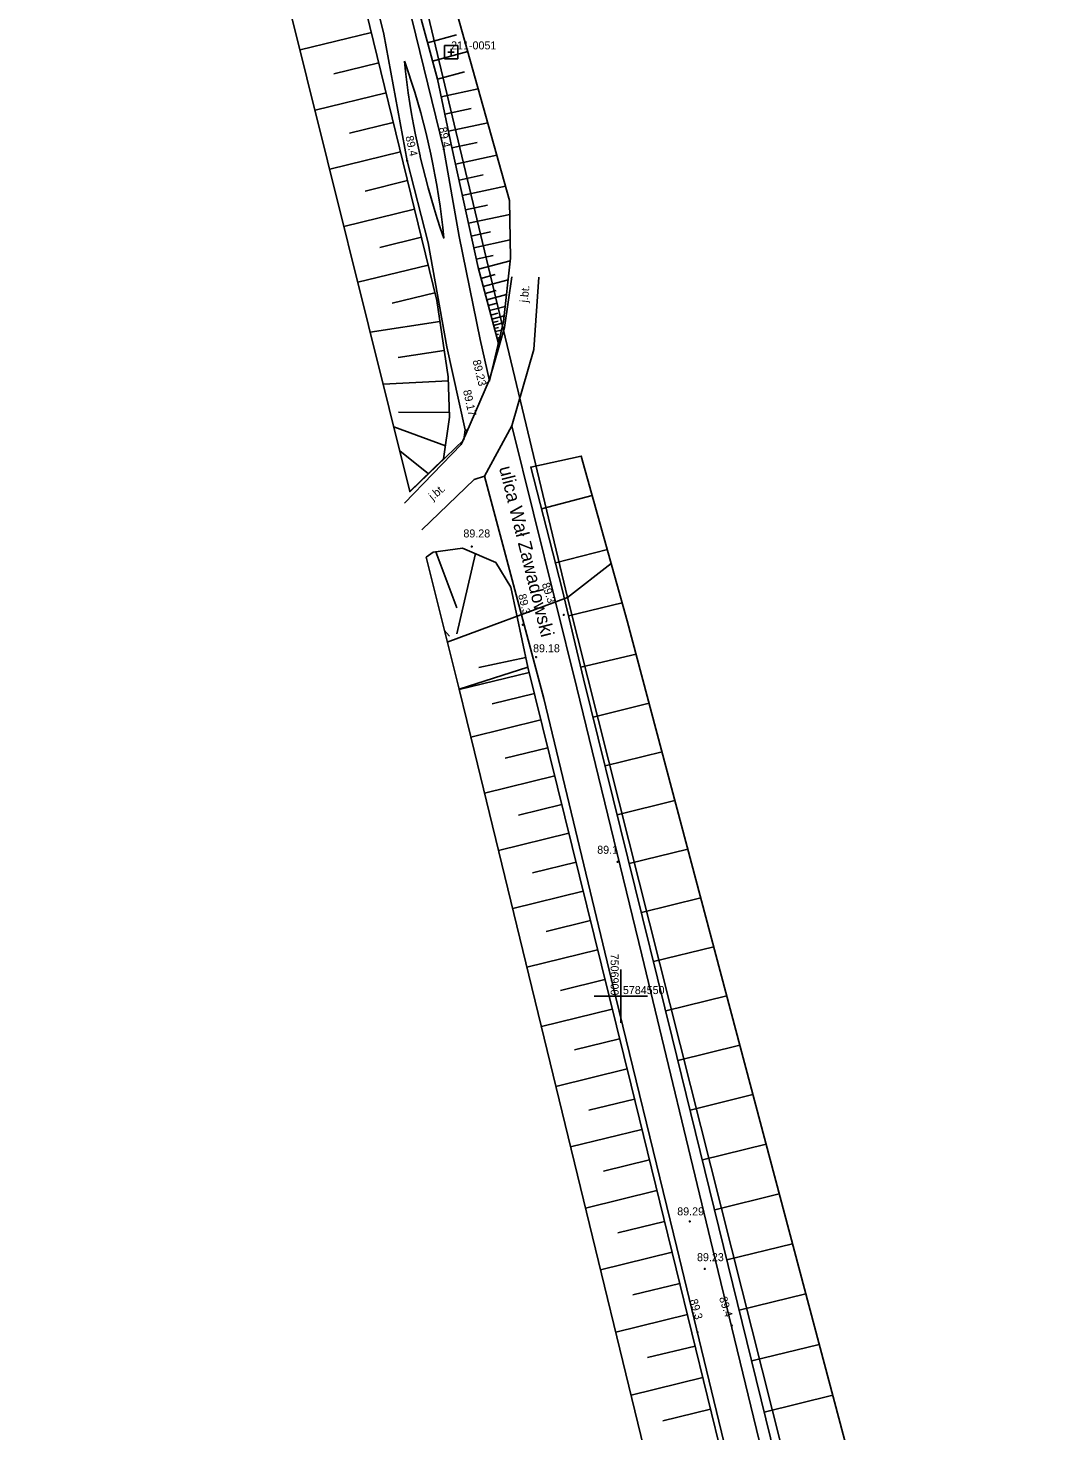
# Model space of a CAD drawing. Extents: x 7506075 to 7506993, y 5784375 to 5786367.
# Drawn here: x 7506844.5 to 7506940.4, y 5784509.3 to 5784640.7 of the extents above; entities that cross this region are included whole.
import ezdxf

# ---------------------------------------------------------------- set-up
doc = ezdxf.new("R2010")
doc.units = 0
for name, color, linetype in [('000 Inne (niezydentyfikowane)', 7, 'Continuous'), ('203-punkt graniczny', 7, 'Continuous'), ('216-obręb ewidencyjny', 7, 'Continuous'), ('218-kontur użytku gruntowego', 7, 'Continuous'), ('219-działka ewidencyjna', 7, 'Continuous'), ('994-Nazwa ulicy', 7, 'Continuous'), ('jezdnia', 7, 'Continuous'), ('jezdnia-Atr17', 7, 'Continuous'), ('pikieta naturalna', 7, 'Continuous'), ('pikieta naturalna-Atr2', 7, 'Continuous'), ('pikieta sztuczna', 7, 'Continuous'), ('pikieta sztuczna-Atr2', 7, 'Continuous'), ('skarpa nieumocniona', 7, 'Continuous'), ('skarpa umocniona', 7, 'Continuous'), ('Szczegółowa osnowa geodezyjna pozioma', 7, 'Continuous'), ('Szczegółowa osnowa geodezyjna pozioma-Atr103', 7, 'Continuous'), ('Wstawianie ramki sekcyjnej z opisem', 7, 'Continuous')]:
    doc.layers.add(name, color=color, linetype=linetype)

# ---------------------------------------------------------------- blocks, each defined once
blk = doc.blocks.new('PW01')
blk.add_circle((0, 0), 0.045)
blk = doc.blocks.new('203')
blk.add_circle((0, 0), 0.045)
blk = doc.blocks.new('OSSP')
for p, q in [((-0.626, 0.625), (-0.626, -0.625)), ((-0.626, 0.625), (-0.626, -0.625)), ((0.624, 0.625), (-0.626, 0.625)), ((0.624, 0.625), (-0.626, 0.625)), ((0.3, 0), (-0.3, 0)), ((0.3, 0), (-0.3, 0)), ((0, -0.3), (0, 0.3)), ((0, -0.3), (0, 0.3)), ((0.624, -0.625), (0.624, 0.625)), ((0.624, -0.625), (0.624, 0.625)), ((-0.626, -0.625), (0.624, -0.625)), ((-0.626, -0.625), (0.624, -0.625))]:
    blk.add_line(p, q)

msp = doc.modelspace()

# ---------------------------------------------------------------- linework, layer by layer
at = {"layer": '000 Inne (niezydentyfikowane)'}
for p, q in [((7506876.63, 5784640.32), (7506869.943, 5784638.687)), ((7506881.89, 5784639.36), (7506884.6, 5784640.09)), ((7506882.36, 5784637.63), (7506885.659, 5784638.524)), ((7506877.32, 5784637.47), (7506873.12, 5784636.44)), ((7506882.81, 5784635.95), (7506885.35, 5784636.64)), ((7506878.01, 5784634.65), (7506871.349, 5784633.029)), ((7506883.17, 5784634.29), (7506886.641, 5784635.023)), ((7506883.51, 5784632.66), (7506885.97, 5784633.18)), ((7506878.68, 5784631.87), (7506874.59, 5784630.88)), ((7506883.85, 5784631.06), (7506887.533, 5784631.839)), ((7506879.35, 5784629.13), (7506872.72, 5784627.514)), ((7506884.18, 5784629.5), (7506886.54, 5784630.01)), ((7506884.51, 5784627.97), (7506888.383, 5784628.807)), ((7506880.01, 5784626.43), (7506876.03, 5784625.46)), ((7506884.84, 5784626.48), (7506887.1, 5784626.97)), ((7506885.15, 5784625.04), (7506889.192, 5784625.922)), ((7506880.66, 5784623.76), (7506874.053, 5784622.148)), ((7506885.45, 5784623.69), (7506887.51, 5784624.14)), ((7506885.72, 5784622.43), (7506889.59, 5784623.27)), ((7506881.31, 5784621.12), (7506877.42, 5784620.18)), ((7506885.98, 5784621.24), (7506887.8, 5784621.64)), ((7506886.22, 5784620.13), (7506889.64, 5784620.87)), ((7506881.94, 5784618.52), (7506875.354, 5784616.914)), ((7506886.45, 5784619.08), (7506888.05, 5784619.43)), ((7506886.67, 5784618.12), (7506889.64, 5784618.91)), ((7506886.9, 5784617.27), (7506888.22, 5784617.62)), ((7506887.1, 5784616.51), (7506889.45, 5784617.14)), ((7506882.58, 5784615.91), (7506878.57, 5784614.94)), ((7506887.28, 5784615.84), (7506888.32, 5784616.12)), ((7506887.44, 5784615.25), (7506889.29, 5784615.75)), ((7506887.58, 5784614.72), (7506888.4, 5784614.94)), ((7506887.71, 5784614.25), (7506889.17, 5784614.64)), ((7506883.05, 5784613.23), (7506876.516, 5784612.237)), ((7506887.82, 5784613.83), (7506888.47, 5784614.01)), ((7506887.92, 5784613.46), (7506889.07, 5784613.77)), ((7506888.01, 5784613.14), (7506888.52, 5784613.27)), ((7506888.08, 5784612.85), (7506888.98, 5784613.09)), ((7506888.15, 5784612.58), (7506888.53, 5784612.68)), ((7506888.24, 5784612.28), (7506888.82, 5784612.43)), ((7506888.32, 5784611.97), (7506888.53, 5784612.03)), ((7506888.4, 5784611.66), (7506888.66, 5784611.73)), ((7506883.46, 5784610.51), (7506879.15, 5784609.86)), ((7506883.84, 5784607.67), (7506877.727, 5784607.366)), ((7506883.95, 5784604.69), (7506879.16, 5784604.74)), ((7506883.58, 5784601.58), (7506878.723, 5784603.358)), ((7506881.98, 5784598.97), (7506879.285, 5784601.096)), ((7506892.57, 5784595.69), (7506897.321, 5784596.922)), ((7506882.67, 5784591.64), (7506884.64, 5784586.41)), ((7506886.37, 5784591.49), (7506884.65, 5784583.95)), ((7506893.88, 5784590.6), (7506898.741, 5784591.856)), ((7506895.11, 5784585.65), (7506900.144, 5784586.852)), ((7506883.458, 5784584.305), (7506883.94, 5784583.73)), ((7506891.11, 5784581.73), (7506886.7, 5784580.8)), ((7506896.26, 5784580.83), (7506901.439, 5784582.064)), ((7506891.42, 5784580.35), (7506884.844, 5784578.73)), ((7506891.91, 5784578.38), (7506887.94, 5784577.4)), ((7506897.41, 5784576.15), (7506902.663, 5784577.45)), ((7506892.52, 5784575.9), (7506885.949, 5784574.284)), ((7506893.16, 5784573.29), (7506889.16, 5784572.3)), ((7506898.54, 5784571.58), (7506903.87, 5784572.898)), ((7506893.82, 5784570.64), (7506887.238, 5784569.015)), ((7506899.67, 5784567.01), (7506905.076, 5784568.354)), ((7506894.48, 5784567.96), (7506890.43, 5784566.96)), ((7506895.14, 5784565.27), (7506888.546, 5784563.642)), ((7506900.8, 5784562.43), (7506906.287, 5784563.79)), ((7506895.81, 5784562.56), (7506891.72, 5784561.55)), ((7506896.48, 5784559.83), (7506889.869, 5784558.207)), ((7506901.94, 5784557.84), (7506907.5, 5784559.214)), ((7506897.16, 5784557.1), (7506893.02, 5784556.08)), ((7506897.83, 5784554.35), (7506891.208, 5784552.708)), ((7506903.07, 5784553.24), (7506908.715, 5784554.634)), ((7506898.52, 5784551.58), (7506894.34, 5784550.55)), ((7506904.22, 5784548.62), (7506909.936, 5784550.032)), ((7506899.2, 5784548.8), (7506892.559, 5784547.156)), ((7506899.89, 5784546), (7506895.67, 5784544.96)), ((7506905.36, 5784543.98), (7506911.163, 5784545.405)), ((7506900.59, 5784543.19), (7506893.925, 5784541.543)), ((7506906.5, 5784539.33), (7506912.391, 5784540.775)), ((7506901.28, 5784540.36), (7506897.01, 5784539.31)), ((7506901.98, 5784537.52), (7506895.304, 5784535.88)), ((7506907.65, 5784534.67), (7506913.622, 5784536.135)), ((7506902.68, 5784534.66), (7506898.37, 5784533.6)), ((7506903.39, 5784531.79), (7506896.699, 5784530.148)), ((7506908.8, 5784529.98), (7506914.858, 5784531.475)), ((7506904.1, 5784528.9), (7506899.74, 5784527.83)), ((7506909.95, 5784525.28), (7506916.1, 5784526.791)), ((7506904.81, 5784526), (7506898.109, 5784524.355)), ((7506905.52, 5784523.09), (7506901.12, 5784522.01)), ((7506911.11, 5784520.57), (7506917.345, 5784522.098)), ((7506906.24, 5784520.16), (7506899.53, 5784518.52)), ((7506906.96, 5784517.22), (7506902.52, 5784516.13)), ((7506912.27, 5784515.82), (7506918.599, 5784517.373)), ((7506907.68, 5784514.26), (7506900.965, 5784512.625)), ((7506913.45, 5784511.03), (7506919.863, 5784512.608)), ((7506908.41, 5784511.3), (7506903.93, 5784510.2))]:
    msp.add_line(p, q, dxfattribs=at)
at = {"layer": '216-obręb ewidencyjny'}
for points in [[(7506895.02, 5784587.37), (7506880.51, 5784647.95)], [(7506895.02, 5784587.37), (7506883.74, 5784583.171)], [(7506940.165, 5784408.278), (7506895.02, 5784587.37)]]:
    msp.add_lwpolyline(points, dxfattribs=at)
at = {"layer": '218-kontur użytku gruntowego'}
for points in [[(7506895.02, 5784587.37), (7506880.51, 5784647.95)], [(7506883.74, 5784583.171), (7506895.02, 5784587.37)], [(7506895.02, 5784587.37), (7506940.165, 5784408.278)]]:
    msp.add_lwpolyline(points, dxfattribs=at)
at = {"layer": '219-działka ewidencyjna'}
for points in [[(7506895.02, 5784587.37), (7506880.51, 5784647.95)], [(7506895.02, 5784587.37), (7506880.51, 5784647.95)], [(7506895.02, 5784587.37), (7506899.111, 5784590.537)], [(7506895.02, 5784587.37), (7506883.74, 5784583.171)], [(7506883.74, 5784583.171), (7506895.02, 5784587.37)], [(7506940.165, 5784408.278), (7506895.02, 5784587.37)], [(7506940.165, 5784408.278), (7506895.02, 5784587.37)]]:
    msp.add_lwpolyline(points, dxfattribs=at)
at = {"layer": 'jezdnia'}
for p, q in [((7506889.792, 5784617.412), (7506889.089, 5784612.675)), ((7506891.84, 5784610.615), (7506892.321, 5784617.389)), ((7506889.089, 5784612.675), (7506887.706, 5784607.784)), ((7506889.796, 5784603.456), (7506891.84, 5784610.615)), ((7506885.48, 5784602.658), (7506887.706, 5784607.784)), ((7506885.056, 5784601.715), (7506885.48, 5784602.658)), ((7506887.218, 5784598.723), (7506889.796, 5784603.456)), ((7506895.88, 5784578.885), (7506889.796, 5784603.456)), ((7506879.716, 5784596.202), (7506885.056, 5784601.715)), ((7506886.258, 5784598.437), (7506887.218, 5784598.723)), ((7506887.218, 5784598.723), (7506892.804, 5784577.898)), ((7506886.258, 5784598.437), (7506881.347, 5784593.717)), ((7506901.982, 5784553.885), (7506895.88, 5784578.885)), ((7506892.804, 5784577.898), (7506898.907, 5784552.427)), ((7506908.634, 5784526.274), (7506901.982, 5784553.885)), ((7506898.907, 5784552.427), (7506905.24, 5784526.442)), ((7506905.24, 5784526.442), (7506912.45, 5784496.722)), ((7506915.601, 5784497.452), (7506908.634, 5784526.274))]:
    msp.add_line(p, q, dxfattribs=at)
for points in [[(7506873.05, 5784671.33), (7506880.78, 5784640.05), (7506883.42, 5784629.35), (7506884.86, 5784621.19), (7506886.83, 5784611.55)], [(7506883.71, 5784610.86), (7506881.94, 5784620.61), (7506879.97, 5784628.3), (7506877.8, 5784640.17), (7506870.31, 5784670.67)], [(7506886.83, 5784611.55), (7506887.7, 5784607.66), (7506889.01, 5784613.23), (7506889.67, 5784619.16), (7506889.571, 5784624.569)], [(7506880.237, 5784597.265), (7506885.3, 5784602.15), (7506885.41, 5784603.08), (7506883.71, 5784610.86)]]:
    msp.add_lwpolyline(points, dxfattribs=at)
msp.add_lwpolyline([(7506879.73, 5784637.64), (7506879.84, 5784636.65), (7506879.96, 5784635.65), (7506880.09, 5784634.66), (7506880.24, 5784633.67), (7506880.4, 5784632.69), (7506880.58, 5784631.7), (7506880.77, 5784630.72), (7506880.97, 5784629.74), (7506881.19, 5784628.76), (7506881.21, 5784628.66), (7506881.44, 5784627.69), (7506881.69, 5784626.72), (7506881.94, 5784625.75), (7506882.22, 5784624.79), (7506882.5, 5784623.83), (7506882.8, 5784622.88), (7506883.11, 5784621.93), (7506883.41, 5784621.05), (7506883.31, 5784622.05), (7506883.19, 5784623.04), (7506883.06, 5784624.03), (7506882.91, 5784625.02), (7506882.76, 5784626.01), (7506882.58, 5784626.99), (7506882.39, 5784627.97), (7506882.2, 5784628.91), (7506881.98, 5784629.89), (7506881.75, 5784630.86), (7506881.51, 5784631.83), (7506881.25, 5784632.8), (7506880.98, 5784633.76), (7506880.7, 5784634.72), (7506880.4, 5784635.67), (7506880.08, 5784636.62), (7506879.76, 5784637.57)], close=True, dxfattribs=at)
at = {"layer": 'skarpa nieumocniona'}
msp.add_lwpolyline([(7506888.29, 5784590.66), (7506889.71, 5784588.32), (7506891.3, 5784580.84), (7506884.84, 5784578.76), (7506881.76, 5784591.14), (7506882.41, 5784591.6), (7506885.17, 5784592)], close=True, dxfattribs=at)
at = {"layer": 'skarpa umocniona'}
for points in [[(7506852.18, 5784779.3), (7506868.65, 5784704.71), (7506880.2, 5784658), (7506889.57, 5784624.57), (7506889.67, 5784619.16), (7506889.01, 5784613.23), (7506888.53, 5784611.18), (7506886.62, 5784618.3), (7506884.17, 5784629.55), (7506882.82, 5784635.93), (7506878.57, 5784651.6), (7506876.16, 5784660.02), (7506872.84, 5784673.6), (7506869.37, 5784689.41), (7506862.11, 5784719.93), (7506850.92, 5784763.97), (7506846.72, 5784779.03), (7506848.27, 5784785.27), (7506850.57, 5784785.8)], [(7506852.18, 5784779.3), (7506868.65, 5784704.71), (7506880.2, 5784658), (7506889.57, 5784624.57), (7506889.67, 5784619.16), (7506889.01, 5784613.23), (7506888.53, 5784611.18), (7506886.62, 5784618.3), (7506884.17, 5784629.55), (7506882.82, 5784635.93), (7506878.57, 5784651.6), (7506876.16, 5784660.02), (7506872.84, 5784673.6), (7506869.37, 5784689.41), (7506862.11, 5784719.93), (7506850.92, 5784763.97), (7506846.72, 5784779.03), (7506848.27, 5784785.27), (7506850.57, 5784785.8)], [(7506846.87, 5784760.9), (7506848.5, 5784753.88), (7506851.4, 5784741.77), (7506856.01, 5784722.5), (7506859.35, 5784709.08), (7506862.08, 5784697.31), (7506866.86, 5784677.84), (7506875.08, 5784646.66), (7506882.75, 5784615.2), (7506883.83, 5784608.06), (7506883.96, 5784604.28), (7506883.4, 5784600.35), (7506880.23, 5784597.29), (7506868.65, 5784643.89), (7506850.59, 5784726.01), (7506846.12, 5784744.79), (7506844.68, 5784762.93), (7506844.45, 5784767.49), (7506844.55, 5784770.15)], [(7506846.87, 5784760.9), (7506848.5, 5784753.88), (7506851.4, 5784741.77), (7506856.01, 5784722.5), (7506859.35, 5784709.08), (7506862.08, 5784697.31), (7506866.86, 5784677.84), (7506875.08, 5784646.66), (7506882.75, 5784615.2), (7506883.83, 5784608.06), (7506883.96, 5784604.28), (7506883.4, 5784600.35), (7506880.23, 5784597.29), (7506868.65, 5784643.89), (7506850.59, 5784726.01), (7506846.12, 5784744.79), (7506844.68, 5784762.93), (7506844.45, 5784767.49), (7506844.55, 5784770.15)], [(7506900.61, 5784585.19), (7506925.52, 5784491.28), (7506940.41, 5784439.23), (7506930.2, 5784443.14), (7506926.62, 5784456.37), (7506921.03, 5784480.14), (7506904.83, 5784546.14), (7506896.52, 5784579.73), (7506894.51, 5784588.16), (7506891.56, 5784599.59), (7506896.29, 5784600.62)], [(7506900.61, 5784585.19), (7506925.52, 5784491.28), (7506940.41, 5784439.23), (7506930.2, 5784443.14), (7506926.62, 5784456.37), (7506921.03, 5784480.14), (7506904.83, 5784546.14), (7506896.52, 5784579.73), (7506894.51, 5784588.16), (7506891.56, 5784599.59), (7506896.29, 5784600.62)], [(7506900.96, 5784541.67), (7506905.19, 5784524.45), (7506912.52, 5784494.47), (7506915.39, 5784482.73), (7506921.87, 5784455.55), (7506927.68, 5784431.4), (7506934.36, 5784407.52), (7506928.48, 5784406.75), (7506911.83, 5784467.99), (7506886.29, 5784572.91), (7506884.84, 5784578.76), (7506891.3, 5784580.84)], [(7506900.96, 5784541.67), (7506905.19, 5784524.45), (7506912.52, 5784494.47), (7506915.39, 5784482.73), (7506921.87, 5784455.55), (7506927.68, 5784431.4), (7506934.36, 5784407.52), (7506928.48, 5784406.75), (7506911.83, 5784467.99), (7506886.29, 5784572.91), (7506884.84, 5784578.76), (7506891.3, 5784580.84)]]:
    msp.add_lwpolyline(points, close=True, dxfattribs=at)
at = {"layer": 'Wstawianie ramki sekcyjnej z opisem'}
for points in [[(7506900, 5784547.5), (7506900, 5784552.5)], [(7506897.5, 5784550), (7506902.5, 5784550)]]:
    msp.add_lwpolyline(points, dxfattribs=at)

# ---------------------------------------------------------------- block references
at = {"layer": '203-punkt graniczny'}
msp.add_blockref('203', (7506895.02, 5784587.37), dxfattribs=at)
at = {"layer": 'pikieta naturalna'}
for p in [(7506883.42, 5784629.35), (7506879.97, 5784628.3), (7506894.65, 5784585.74), (7506890.82, 5784584.81), (7506899.7, 5784562.58), (7506907.19, 5784518.52), (7506910.42, 5784519.13)]:
    msp.add_blockref('PW01', p, dxfattribs=at)
at = {"layer": 'pikieta sztuczna'}
for p in [(7506887.48, 5784607.46), (7506885.54, 5784603.02), (7506886.04, 5784592.13), (7506892.07, 5784581.78), (7506906.46, 5784528.9), (7506907.87, 5784524.44)]:
    msp.add_blockref('PW01', p, dxfattribs=at)
at = {"layer": 'Szczegółowa osnowa geodezyjna pozioma'}
msp.add_blockref('OSSP', (7506884.1, 5784638.48), dxfattribs=at)

# ---------------------------------------------------------------- texts
at = {"layer": '994-Nazwa ulicy'}
msp.add_text('ulica Wał Zawadowski', height=1.25, rotation=284.003, dxfattribs=at).set_placement((7506888.586, 5784599.521))
at = {"layer": 'jezdnia-Atr17'}
for rotation, p in [(83.884, (7506891.278, 5784614.988)), (83.884, (7506891.278, 5784614.988)), (83.884, (7506891.278, 5784614.988)), (39.41657, (7506882.375, 5784596.434))]:
    msp.add_text('j.bt.', height=0.75, rotation=rotation, dxfattribs=at).set_placement(p)
at = {"layer": 'pikieta naturalna-Atr2'}
for s, rotation, p in [('89.4', 281.835, (7506882.943, 5784631.376)), ('89.4', 283.029, (7506879.812, 5784630.551)), ('89.3', 287.594, (7506892.592, 5784588.629)), ('89.3', 284.16, (7506890.375, 5784587.606)), ('89.3', 286.088, (7506906.451, 5784521.507)), ('89.4', 287.822, (7506909.202, 5784521.718))]:
    msp.add_text(s, height=0.75, rotation=rotation, dxfattribs=at).set_placement(p)
msp.add_text('89.1', height=0.75, dxfattribs=at).set_placement((7506897.792, 5784563.348))
at = {"layer": 'pikieta sztuczna-Atr2'}
for s, rotation, p in [('89.23', 283.492, (7506886.111, 5784609.556)), ('89.17', 282.355, (7506885.215, 5784606.75))]:
    msp.add_text(s, height=0.75, rotation=rotation, dxfattribs=at).set_placement(p)
for s, p in [('89.28', (7506885.251, 5784592.993)), ('89.18', (7506891.781, 5784582.232)), ('89.29', (7506905.292, 5784529.461)), ('89.23', (7506907.145, 5784525.169))]:
    msp.add_text(s, height=0.75, dxfattribs=at).set_placement(p)
at = {"layer": 'Szczegółowa osnowa geodezyjna pozioma-Atr103'}
msp.add_text('211-0051', height=0.75, dxfattribs=at).set_placement((7506884.1, 5784638.73))
at = {"layer": 'Wstawianie ramki sekcyjnej z opisem'}
for s, rotation, p in [('7506900', 270, (7506899.05, 5784553.981)), ('5784550', 0.001, (7506900.2, 5784550.2))]:
    msp.add_text(s, height=0.75, rotation=rotation, dxfattribs=at).set_placement(p)

doc.saveas('drawing.dxf')
